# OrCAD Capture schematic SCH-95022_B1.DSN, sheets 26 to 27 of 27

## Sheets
26 Page24 IO-EXP/PCIE SDIO MUX: size A2
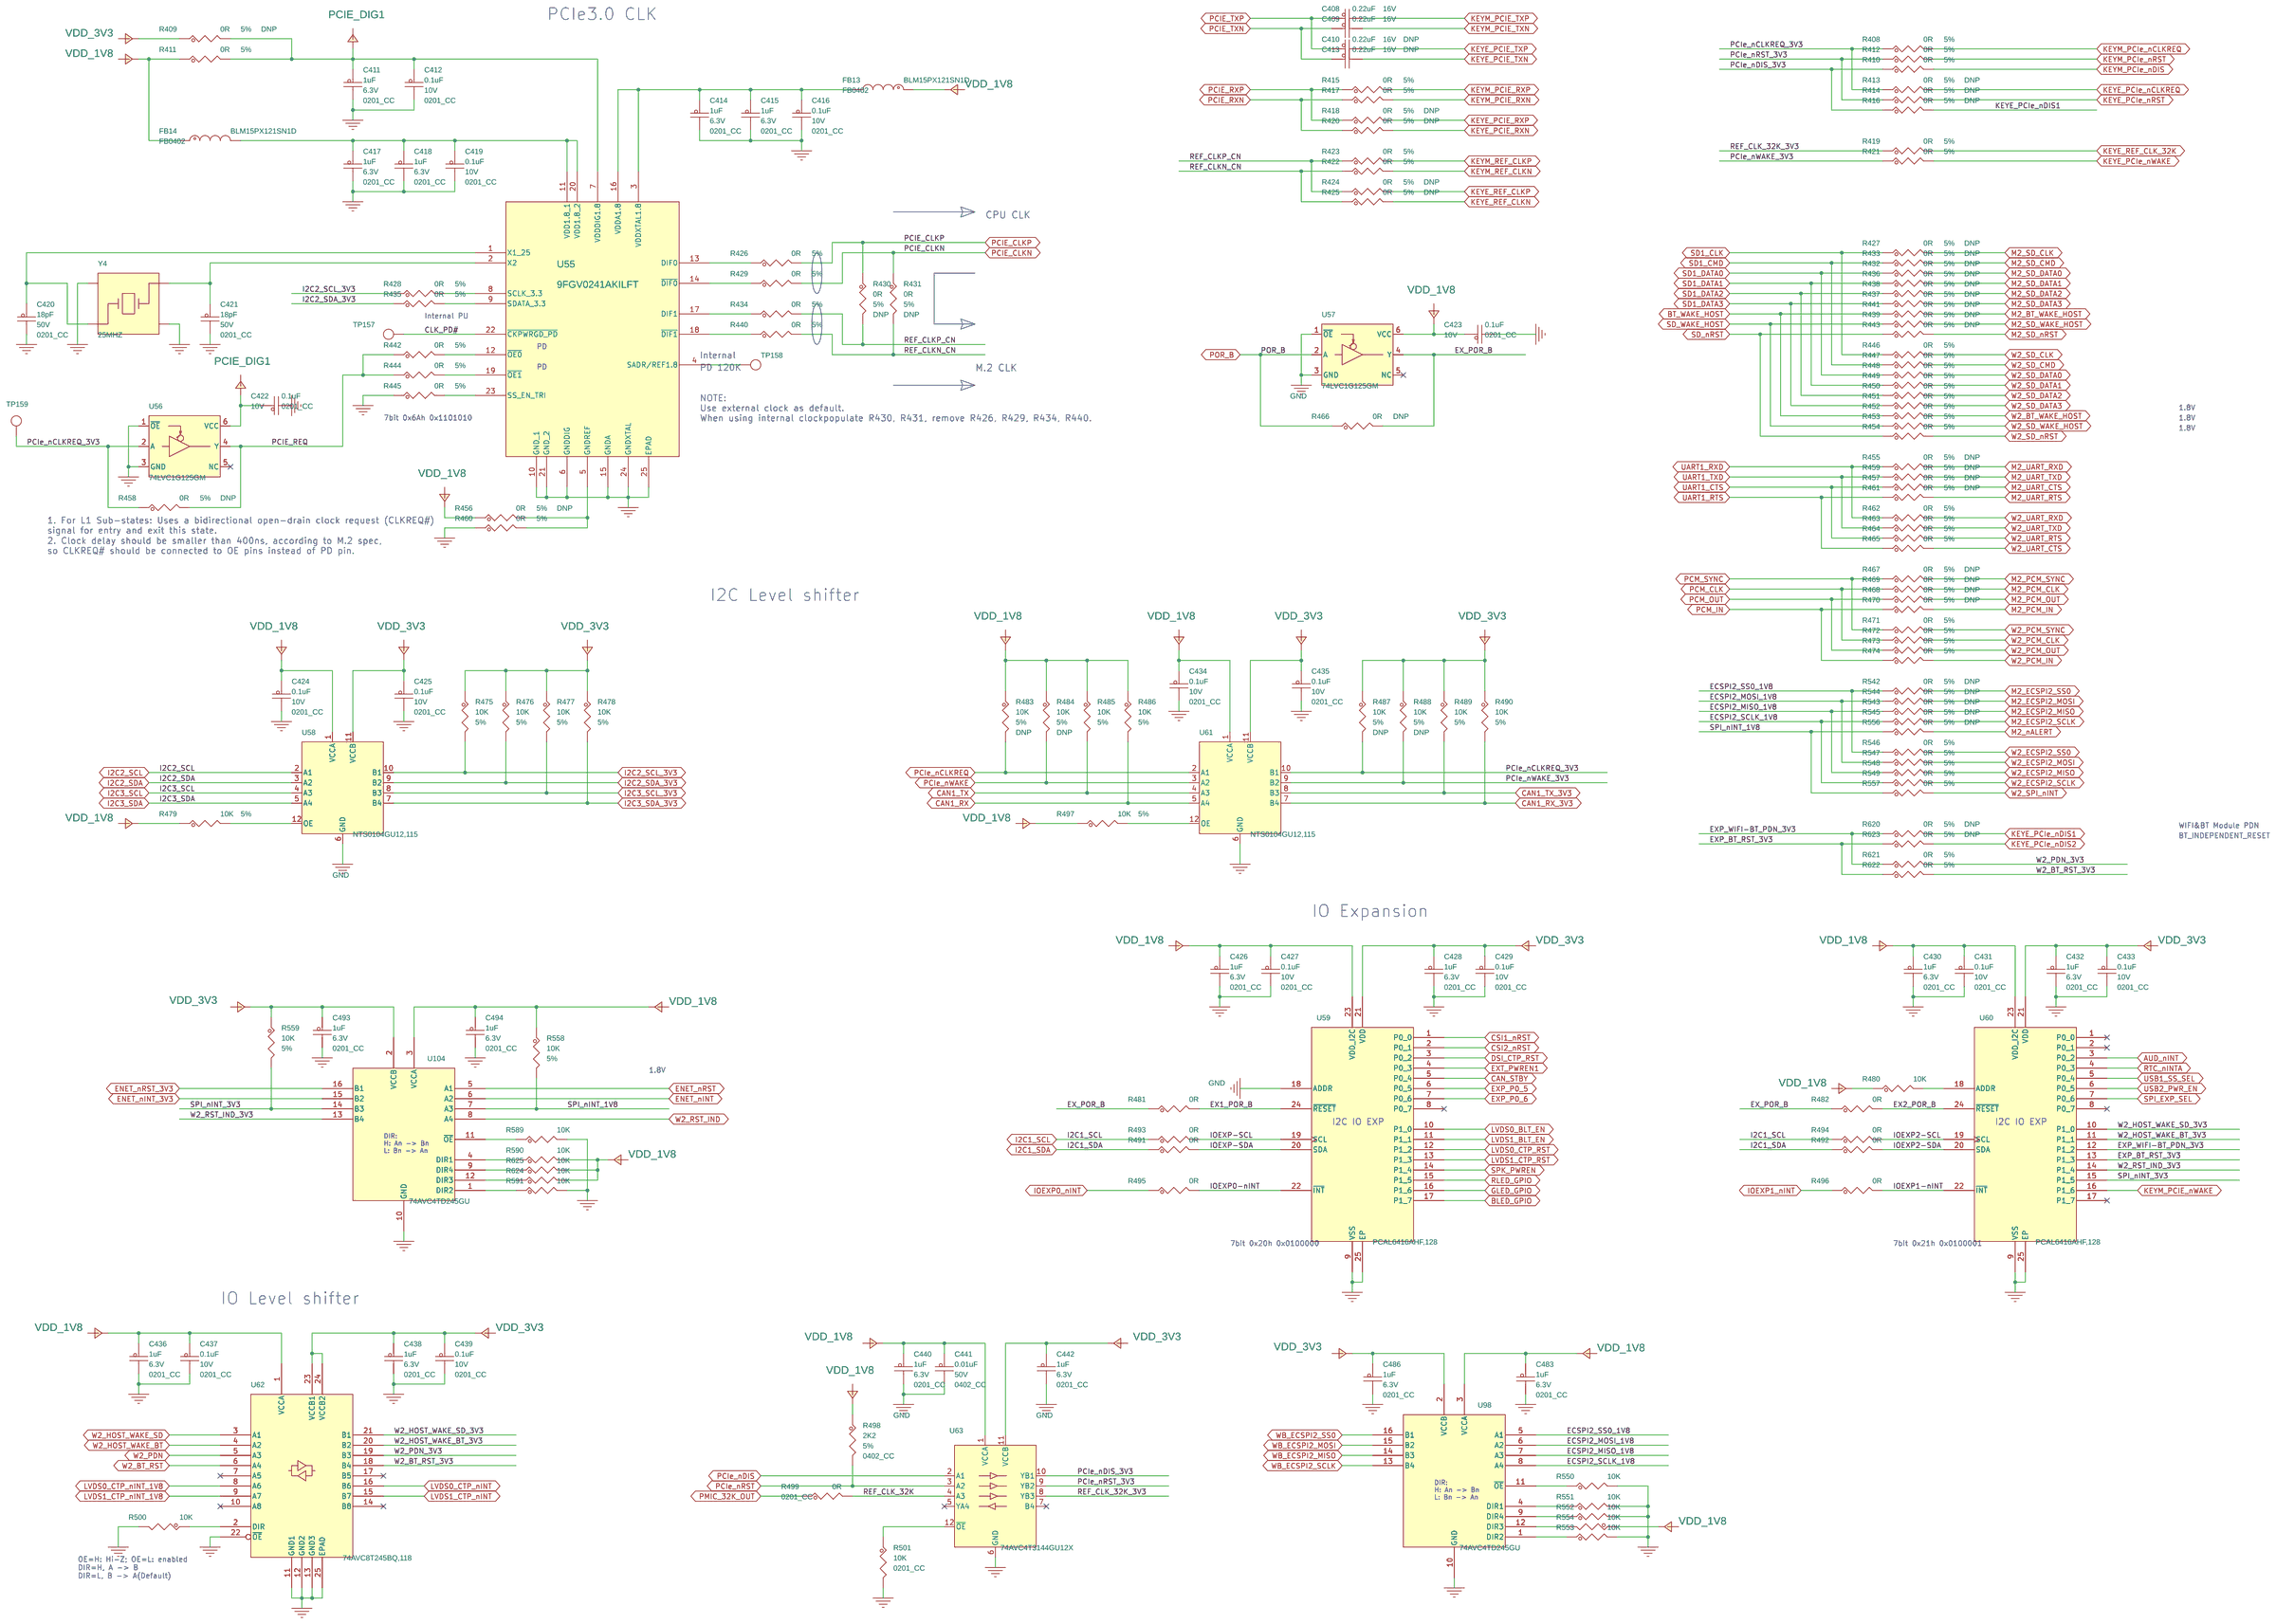
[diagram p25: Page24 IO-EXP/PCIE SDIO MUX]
27 Page21 MicroSD/EXP/BUTTON/LED: size C
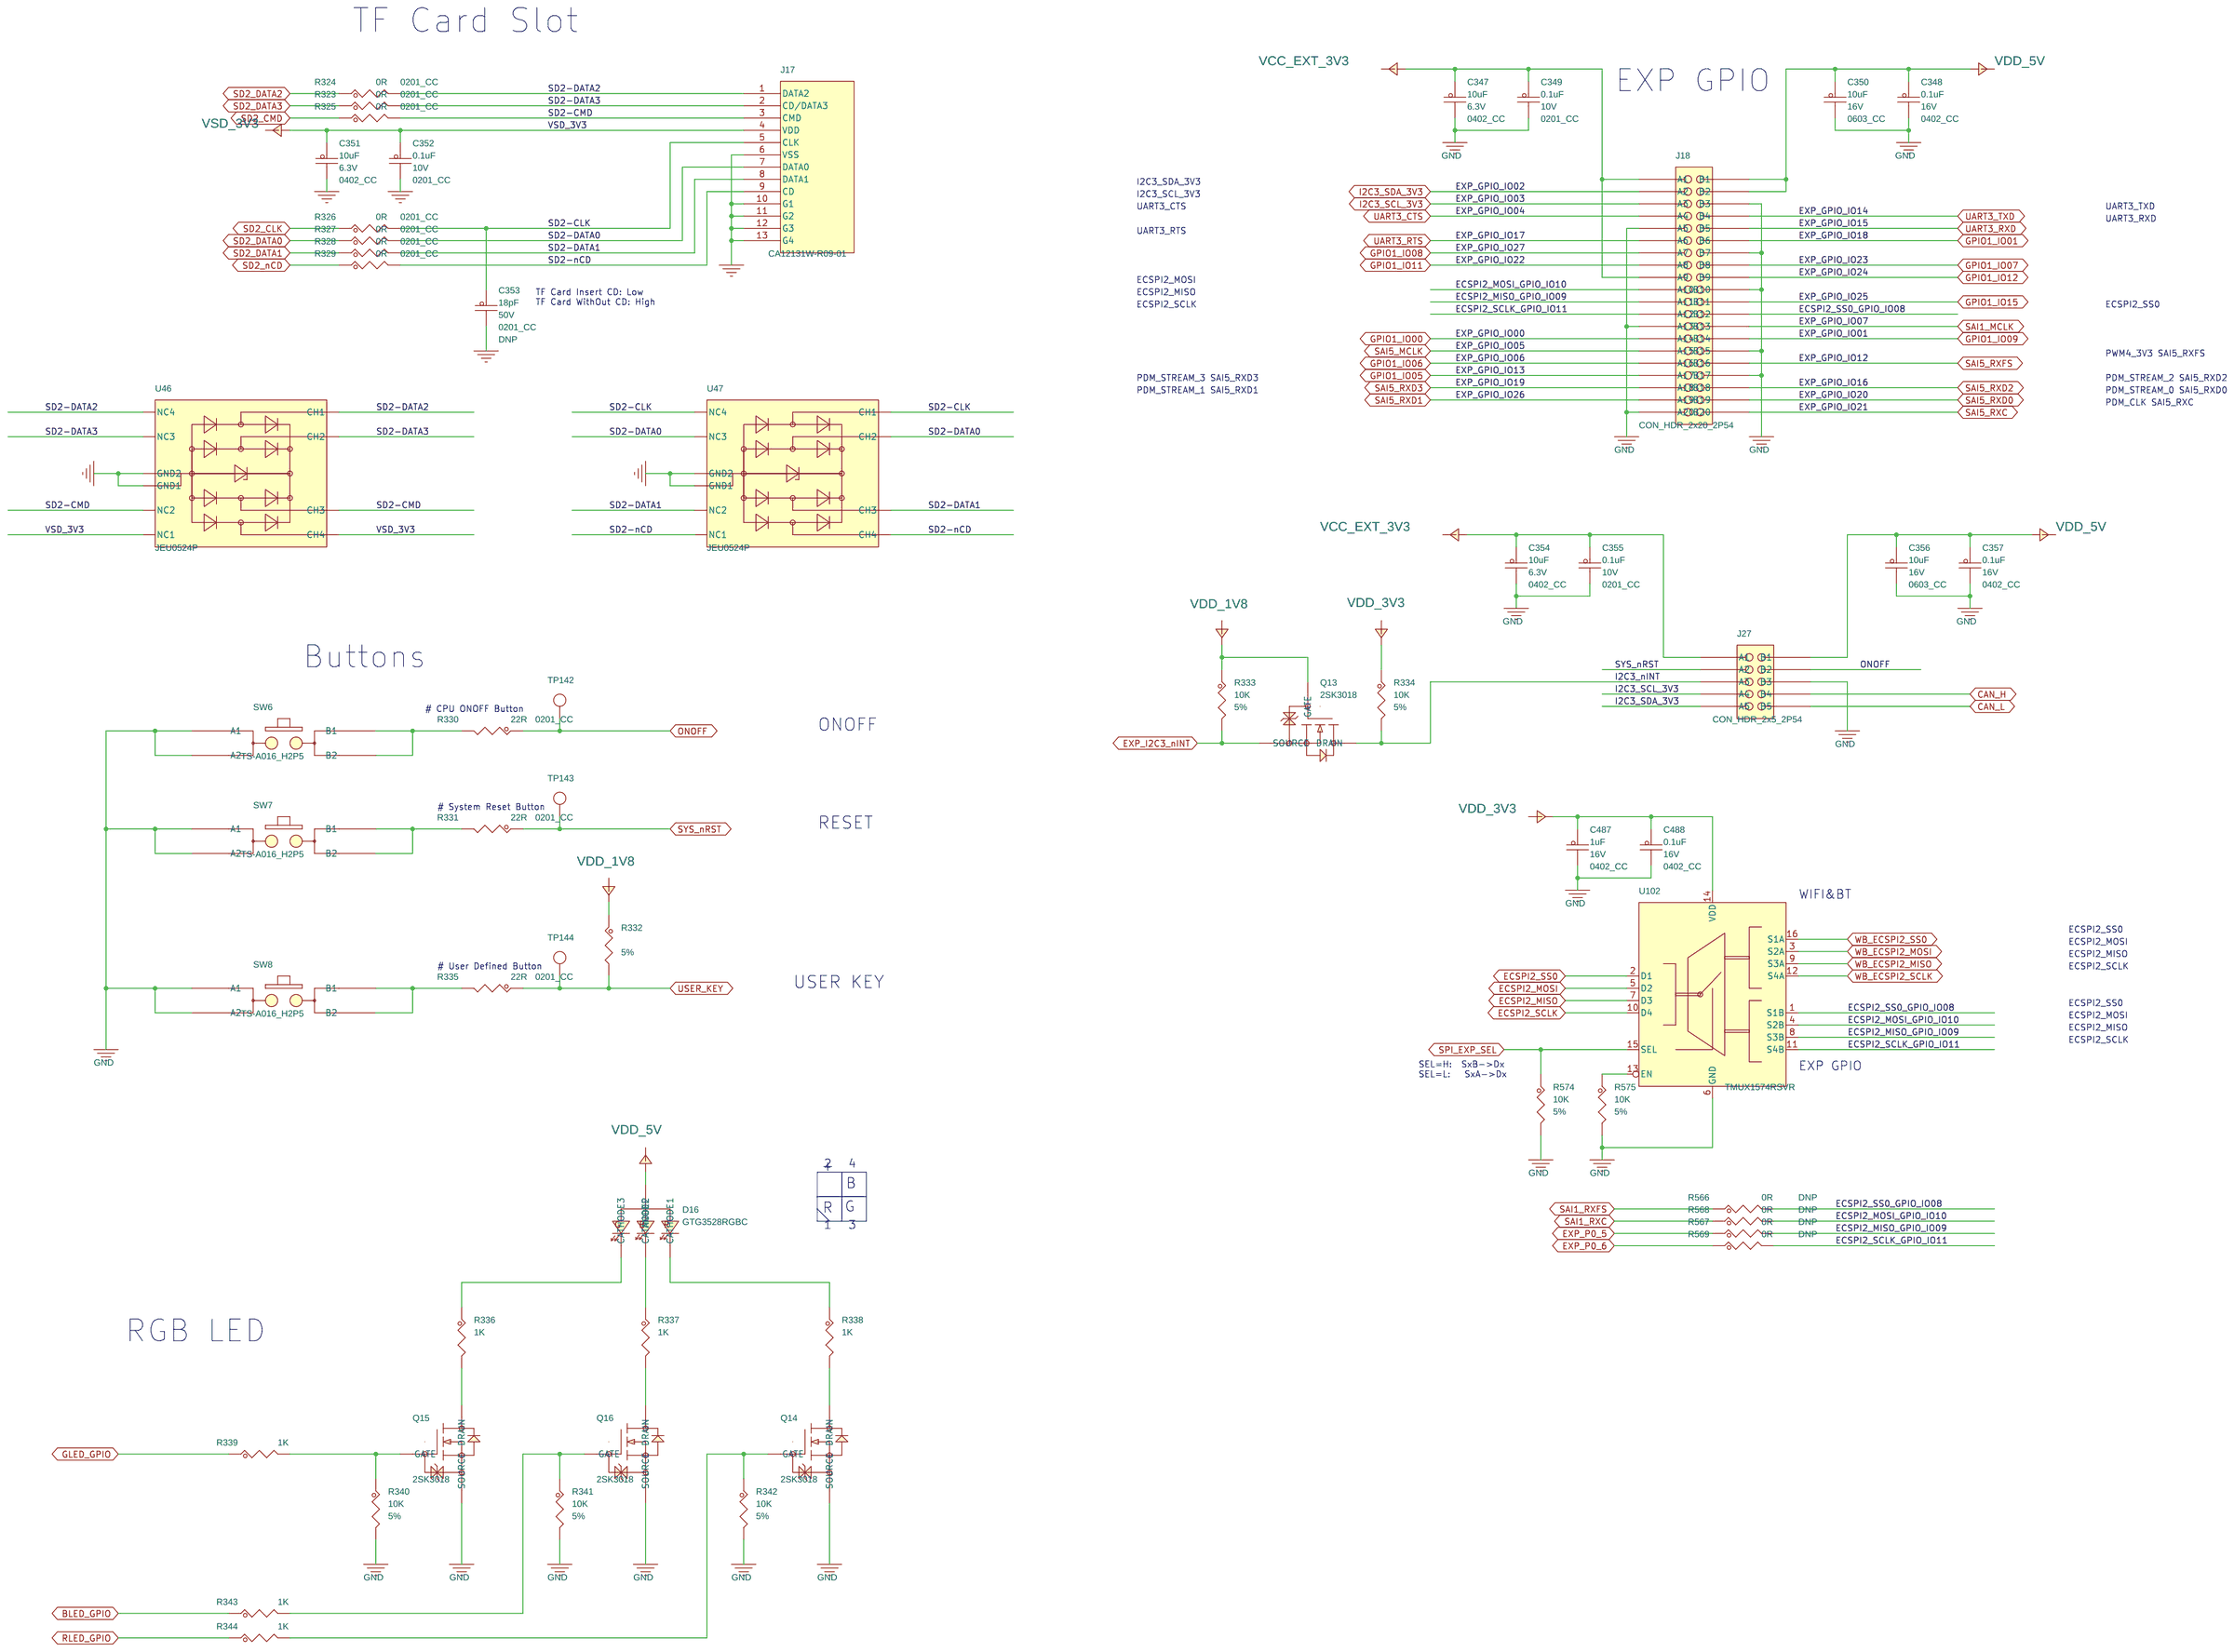
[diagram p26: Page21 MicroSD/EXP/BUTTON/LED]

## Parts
sheet Page21 MicroSD/EXP/BUTTON/LED
C347  10uF  [0402_CC]
C348  0.1uF  [0402_CC]
C349  0.1uF  [0201_CC]
C350  10uF  [0603_CC]
C351  10uF  [0402_CC]
C352  0.1uF  [0201_CC]
C353  18pF  [0201_CC]
C354  10uF  [0402_CC]
C355  0.1uF  [0201_CC]
C356  10uF  [0603_CC]
C357  0.1uF  [0402_CC]
C487  1uF  [0402_CC]
C488  0.1uF  [0402_CC]
D16  GTG3528RGBC  [led4_3p4x3_sm]
J17  CA12131W-R09-01  [MICROSD_14R75x14R50x2R00]
J18  CON_HDR_2x20_2P54  [DIP_HDR2x20_2P54]
J27  CON_HDR_2x5_2P54  [CON_2P54_2x5]
Q13  2SK3018  [SOT_323]
Q14  2SK3018  [SOT_323]
Q15  2SK3018  [SOT_323]
Q16  2SK3018  [SOT_323]
R323  0R  [0201_CC]
R324  0R  [0201_CC]
R325  0R  [0201_CC]
R326  0R  [0201_CC]
R327  0R  [0201_CC]
R328  0R  [0201_CC]
R329  0R  [0201_CC]
R330  22R  [0201_CC]
R331  22R  [0201_CC]
R332  100K  [0402_CC]
R333  10K  [0402_CC]
R334  10K  [0402_CC]
R335  22R  [0201_CC]
R336  1K  [0402_CC]
R337  1K  [0402_CC]
R338  1K  [0402_CC]
R339  1K  [0402_CC]
R340  10K  [0402_CC]
R341  10K  [0402_CC]
R342  10K  [0402_CC]
R343  1K  [0402_CC]
R344  1K  [0402_CC]
R566  0R  [0402_CC]
R567  0R  [0402_CC]
R568  0R  [0402_CC]
R569  0R  [0402_CC]
R574  10K  [0402_CC]
R575  10K  [0402_CC]
SW6  TS-A016_H2P5  [KEY_SMT_4R20x3R25x3R50]
SW7  TS-A016_H2P5  [KEY_SMT_4R20x3R25x3R50]
SW8  TS-A016_H2P5  [KEY_SMT_4R20x3R25x3R50]
TP142  TPAD_020  [tpad_020]
TP143  TPAD_020  [tpad_020]
TP144  TPAD_020  [tpad_020]
U46  JEU0524P  [SLP2510P8-10]
U47  JEU0524P  [SLP2510P8-10]
U102  TMUX1574RSVR  [pqfn16_0p4_2p65x1p85]
sheet Page24 IO-EXP/PCIE SDIO MUX
C408  0.22uF  [0402_CC]
C409  0.22uF  [0402_CC]
C410  0.22uF  [0402_CC]
C411  1uF  [0201_CC]
C412  0.1uF  [0201_CC]
C413  0.22uF  [0402_CC]
C414  1uF  [0201_CC]
C415  1uF  [0201_CC]
C416  0.1uF  [0201_CC]
C417  1uF  [0201_CC]
C418  1uF  [0201_CC]
C419  0.1uF  [0201_CC]
C420  18pF  [0201_CC]
C421  18pF  [0201_CC]
C422  0.1uF  [0201_CC]
C423  0.1uF  [0201_CC]
C424  0.1uF  [0201_CC]
C425  0.1uF  [0201_CC]
C426  1uF  [0201_CC]
C427  0.1uF  [0201_CC]
C428  1uF  [0201_CC]
C429  0.1uF  [0201_CC]
C430  1uF  [0201_CC]
C431  0.1uF  [0201_CC]
C432  1uF  [0201_CC]
C433  0.1uF  [0201_CC]
C434  0.1uF  [0201_CC]
C435  0.1uF  [0201_CC]
C436  1uF  [0201_CC]
C437  0.1uF  [0201_CC]
C438  1uF  [0201_CC]
C439  0.1uF  [0201_CC]
C440  1uF  [0201_CC]
C441  0.01uF  [0402_CC]
C442  1uF  [0201_CC]
C483  1uF  [0201_CC]
C486  1uF  [0201_CC]
C493  1uF  [0201_CC]
C494  1uF  [0201_CC]
FB13  BLM15PX121SN1D  [FB0402]
FB14  BLM15PX121SN1D  [FB0402]
R408  0R  [0402_CC]
R409  0R  [0402_CC]
R410  0R  [0402_CC]
R411  0R  [0402_CC]
R412  0R  [0402_CC]
R413  0R  [0402_CC]
R414  0R  [0402_CC]
R415  0R  [0402_CC]
R416  0R  [0402_CC]
R417  0R  [0402_CC]
R418  0R  [0402_CC]
R419  0R  [0402_CC]
R420  0R  [0402_CC]
R421  0R  [0402_CC]
R422  0R  [0402_CC]
R423  0R  [0402_CC]
R424  0R  [0402_CC]
R425  0R  [0402_CC]
R426  0R  [0402_CC]
R427  0R  [0402_CC]
R428  0R  [0402_CC]
R429  0R  [0402_CC]
R430  0R  [0402_CC]
R431  0R  [0402_CC]
R432  0R  [0402_CC]
R433  0R  [0402_CC]
R434  0R  [0402_CC]
R435  0R  [0402_CC]
R436  0R  [0402_CC]
R437  0R  [0402_CC]
R438  0R  [0402_CC]
R439  0R  [0402_CC]
R440  0R  [0402_CC]
R441  0R  [0402_CC]
R442  0R  [0402_CC]
R443  0R  [0402_CC]
R444  0R  [0402_CC]
R445  0R  [0402_CC]
R446  0R  [0402_CC]
R447  0R  [0402_CC]
R448  0R  [0402_CC]
R449  0R  [0402_CC]
R450  0R  [0402_CC]
R451  0R  [0402_CC]
R452  0R  [0402_CC]
R453  0R  [0402_CC]
R454  0R  [0402_CC]
R455  0R  [0402_CC]
R456  0R  [0402_CC]
R457  0R  [0402_CC]
R458  0R  [0402_CC]
R459  0R  [0402_CC]
R460  0R  [0402_CC]
R461  0R  [0402_CC]
R462  0R  [0402_CC]
R463  0R  [0402_CC]
R464  0R  [0402_CC]
R465  0R  [0402_CC]
R466  0R  [0402_CC]
R467  0R  [0402_CC]
R468  0R  [0402_CC]
R469  0R  [0402_CC]
R470  0R  [0402_CC]
R471  0R  [0402_CC]
R472  0R  [0402_CC]
R473  0R  [0402_CC]
R474  0R  [0402_CC]
R475  10K  [0402_CC]
R476  10K  [0402_CC]
R477  10K  [0402_CC]
R478  10K  [0402_CC]
R479  10K  [0402_CC]
R480  10K  [0402_CC]
R481  0R  [0402_CC]
R482  0R  [0402_CC]
R483  10K  [0402_CC]
R484  10K  [0402_CC]
R485  10K  [0402_CC]
R486  10K  [0402_CC]
R487  10K  [0402_CC]
R488  10K  [0402_CC]
R489  10K  [0402_CC]
R490  10K  [0402_CC]
R491  0R  [0402_CC]
R492  0R  [0402_CC]
R493  0R  [0402_CC]
R494  0R  [0402_CC]
R495  0R  [0402_CC]
R496  0R  [0402_CC]
R497  10K  [0402_CC]
R498  2K2  [0402_CC]
R499  0R  [0201_CC]
R500  10K  [0402_CC]
R501  10K  [0201_CC]
R542  0R  [0402_CC]
R543  0R  [0402_CC]
R544  0R  [0402_CC]
R545  0R  [0402_CC]
R546  0R  [0402_CC]
R547  0R  [0402_CC]
R548  0R  [0402_CC]
R549  0R  [0402_CC]
R550  10K  [0402_CC]
R551  10K  [0402_CC]
R552  10K  [0402_CC]
R553  10K  [0402_CC]
R554  10K  [0402_CC]
R556  0R  [0402_CC]
R557  0R  [0402_CC]
R558  10K  [0402_CC]
R559  10K  [0402_CC]
R589  10K  [0402_CC]
R590  10K  [0402_CC]
R591  10K  [0402_CC]
R620  0R  [0402_CC]
R621  0R  [0402_CC]
R622  0R  [0402_CC]
R623  0R  [0402_CC]
R624  10K  [0402_CC]
R625  10K  [0402_CC]
TP157  TPAD_020  [tpad_020]
TP158  TPAD_020  [tpad_020]
TP159  TPAD_050  [TPAD_050]
U55  9FGV0241AKILFT  [qfn24_0p5_4x4_ep2p2]
U56  74LVC1G125GM  [udfn6_1x1p5mm]
U57  74LVC1G125GM  [udfn6_1x1p5mm]
U58  NTS0104GU12,115  [xqfn12_0p4_1p8x2p1]
U59  PCAL6416AHF,128  [qfn24_4X4_ep2p25mm]
U60  PCAL6416AHF,128  [qfn24_4X4_ep2p25mm]
U61  NTS0104GU12,115  [xqfn12_0p4_1p8x2p1]
U62  74AVC8T245BQ,118  [QFN24_0P5_5P6X3P6_EP]
U63  74AVC4T3144GU12X  [uqfn12_1p7x2mm]
U98  74AVC4TD245GU  [pqfn16_0p4_2p65x1p85]
U104  74AVC4TD245GU  [pqfn16_0p4_2p65x1p85]
Y4  25MHZ  [xtlosc4_3p2x2p5mm_sm]

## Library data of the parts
C347 C351 C354 = CAP_NP: CAP CER 10UF 6.3V 20% X5R 0402; AGILE_PN: 150-79163; CAD_APPROVED: Yes; FPLIST: CC0402_25,CC0402_HD,0402_CC; HEIGHT: 0.65 MM; MFG_NAME01: SAMSUNG; MFG_PN01: CL05A106MQ5NUNC; Polyhex_Number: PD.005.0031; ROHS: Yes; Tolerance: 20%; VOLTAGE: 6.3V
C348 C357 C488 = CAP_NP: CAP CER 0.1UF 16V 10% X5R 0402; CAD_APPROVED: Yes; FPLIST: CC0402_25,CC0402_HD,0402_CC,capc0402_l; HEIGHT: 0.55MM; MFG_NAME01: SAMSUNG; MFG_PN01: CL05B104K05NNNC; Polyhex_Number: PD.005.0036; ROHS: Yes; Tolerance: 10%; VOLTAGE: 16V
C349 C352 C355 C412 C416 C419 C422-C425 C427 C429 C431 C433-C435 C437 C439 = CAP_NP: CAP CER 0.1uF 10V 20% X5R 0201; CAD_APPROVED: Yes; HEIGHT: 0.35MM; MFG_NAME01: SAMSUNG; MFG_PN01: CL03A104KP3NNNC; Package Size: 0201; Package Type: 7” reel; Polyhex_Number: PD.005.0054; ROHS: Yes; Tolerance: 20%; VOLTAGE: 10V
C350 C356 = CAP_NP: CAP CER 10uF 16V 10% X5R 0603; CAD_APPROVED: Yes; HEIGHT: 0.55 MM; MFG_NAME01: SAMSUNG; MFG_PN01: CL10A106MO8NQN; Package Size: 0603; Polyhex_Number: PD.005.0001; ROHS: Yes; Tolerance: 10%; VOLTAGE: 16V
C353 = CAP_NP: CAP CER 18pF 50V 5% C0G 0201; ASSY_OPT: DNP; CAD_APPROVED: Yes; HEIGHT: 0.35MM; MFG_NAME01: SAMSUNG; MFG_PN01: CL03C180JB3NNNH; Package Size: 0201; Package Type: 7” reel; Polyhex_Number: PD.005.0033; ROHS: Yes; Tolerance: 5%; VOLTAGE: 50V
C487 = CAP_NP: CAP CER 1UF 16V 10% X5R 0402; CAD_APPROVED: Yes; FPLIST: CC0402_25,CC0402_HD,0402_CC,capc0402_l; HEIGHT: 0.55MM; MFG_NAME01: SAMSUNG; MFG_PN01: CL05A105KO5NNNC; Polyhex_Number: PD.005.0099; ROHS: Yes; Tolerance: 10%; VOLTAGE: 16V
D16 = LED_GPLY6900: LED RGB MULTI 20MA SMT; AGILE_PN: 370-76731; CAD_APPROVED: Yes; HEIGHT: 2.04 MM; MFG_NAME01: HYXNDQ; Polyhex_Number: PD.020.0076; VOLTAGE: 1.7-3.7V
J17 = TFCARD_SOCKET: CON 9 MICRO SD CARD PUSH SMT 1.9MM; Created by: JJJ; HEIGHT: 1.9mm; MFG_NAME01: JINRUN; Polyhex_Number: PD.010.0025; Priority: A
J18 = CON_HDR_2x20_2P54: CON HEADER PH2.54x2.5 2x20P PA6.0 PC3.0 180 YELLOW; MFG_NAME01: XINGUANHUIELECTRONICS; MFG_PN01: PH1-H220-S9Y-G0; Polyhex_Number: PD.011.0171
J27 = CON_HDR_2X5_2P54: CON HEADER 2X5PIN 2.54MM DIP; MFG_NAME01: WENZHANGJIMEI; MFG_PN01: PH2.54X2.5_2X5P_DIP; Polyhex_Number: PD.011.0173
Q13-Q16 = 2SK3018_SOT323: NMOS SW 30V 100mA SOT-323; MFG_NAME01: CHANGJING ELECTRONICS; Polyhex_Number: PD.014.0008
R323-R329 R499 = RES: RES MF ZERO OHM 1/20W 5% 0201; AGILE_PN: 470-82323; CAD_APPROVED: Yes; FPLIST: RC0201,0201_CC; HEIGHT: 0.26MM; MFG_NAME01: YAGEO; MFG_PN01: RC0201JR-070RL; Polyhex_Number: PD.004.0171; ROHS: Yes; Temp Range: -55°C ~ 125°C; Temp_Range: -55°C ~ 125°C; Tolerance: 5%; VOLTAGE: 25V
R330 R331 R335 = RES: RES MF 22 OHM 1/20W 5% 0201; AGILE_PN: 470-82323; CAD_APPROVED: Yes; FPLIST: RC0201,0201_CC; HEIGHT: 0.26MM; MFG_NAME01: YAGEO; MFG_PN01: RC0201JR-0722RL; Polyhex_Number: PD.004.0173; ROHS: Yes; Temp Range: -55°C ~ 125°C; Temp_Range: -55°C ~ 125°C; Tolerance: 5%; VOLTAGE: 25V
R332 = RES: RES MF 100K 1/16W 5% 0402; AGILE_PN: 470-75597; CAD_APPROVED: Yes; FPLIST: RC0402_25,RC0402_HD,0402_CC; HEIGHT: 0.40 MM; MFG_NAME01: YAGEO; MFG_PN01: RC0402JR-07100KL; Polyhex_Number: PD.004.0004; ROHS: Yes; Temp Range: -55C to +155C; Temp_Range: -55C to +155C; Tolerance: 5%; VOLTAGE: 50V
R333 R334 R340-R342 R475-R480 R485 R486 R489 R490 R497 R500 R550-R554 R558 R559 R574 R575 R589-R591 R624 R625 = RES: RES MF 10K 1/16W 5% 0402; AGILE_PN: 470-75557; CAD_APPROVED: Yes; FPLIST: RC0402_25,RC0402_HD,0402_CC; HEIGHT: 0.4 MM; MFG_NAME01: YAGEO; MFG_PN01: RC0402JR-0710KL; Polyhex_Number: PD.004.0010; ROHS: Yes; Tolerance: 5%; VOLTAGE: 50V
R336-R339 R343 R344 = RES: RES MF 1K 1/16W 5% 0402; CAD_APPROVED: Yes; HEIGHT: 0.4 MM; MFG_NAME01: YAGEO; MFG_PN01: RC0402JR-071KL; Polyhex_Number: PD.004.0007; ROHS: Yes; Tolerance: 5%
R409 R413 R414 R416 R418 R420 R424 R425 R427 R430-R433 R436-R439 R441 R443 R455-R459 R461 R466-R470 R542-R545 R556 R566-R569 R620 R623 = RES: RES MF ZERO OHM 1/16W 5% 0402; AGILE_PN: 470-75394; ASSY_OPT: DNP; CAD_APPROVED: Yes; FPLIST: RC0402_25,RC0402_HD,RC0402_X2,0402_CC; HEIGHT: 0.45 MM; MFG_NAME01: YAGEO; MFG_PN01: RC0402JR-070RL; Polyhex_Number: PD.004.0009; ROHS: Yes; Tolerance: 5%; VOLTAGE: 50V
SW6-SW8 = SW_PB_ESW: SW SPST MOM NO PB TACT 50mA 12V SMT; AGILE_PN: 510-77562; CAD_APPROVED: Yes; HEIGHT: 5MM; MFG_NAME01: HUAXINR; Polyhex_Number: PD.015.0009; ROHS: Yes
TP142-TP144 TP157 TP158 = TESTLOOP: TEST POINT PAD 0.5MM DIA SMT, NO PART TO ORDER; AGILE_PN: 211-77484; ASSY_OPT: DNP; CAD_APPROVED: Yes; HEIGHT: 0.1MM; MFG_NAME01: NOT A COMPONENT; MFG_PN01: NOT A COMPONENT; Polyhex_Number: TEST POINT; ROHS: Yes
U46 U47 = TVS_ARRAY: TVS Diode array for ESD Protection 0.65pF; AGILE_PN: 480-79837; CAD_APPROVED: Yes; EN: 301-0-01726; HEIGHT: 0.5MM; MFG_NAME01: Jiejie Microelectronics; Polyhex_Number: PD.020.0022; ROHS: Yes; Temp Range: -55C to +125C; Temp_Range: -55C to +125C
U102 = TMUX1574RSVR_A: IC MUX SW SPDT 1.8V UQFN16; AGILE_PN: 312-82341; MFG_NAME01: TEXAS INSTRUMENTS; Polyhex_Number: PD.008.0333
C408 C409 = CAP_NP: CAP CER 0.22uF 16V 10% X5R 0402; AGILE_PN: 150-79999; CAD_APPROVED: Yes; FPLIST: CC0402_25,CC0402_HD,0402_CC; HEIGHT: 0.55MM; MFG_NAME01: SAMSUNG; MFG_PN01: CL05B224KO5NNNC; Package Size: 0402; Polyhex_Number: PD.005.0050; ROHS: Yes; Temp Range: -55°C to +85°C; Temp_Range: -55°C to +85°C; Tolerance: 10%; VOLTAGE: 16V
C410 C413 = CAP_NP: CAP CER 0.22uF 16V 10% X5R 0402; AGILE_PN: 150-79999; ASSY_OPT: DNP; CAD_APPROVED: Yes; FPLIST: CC0402_25,CC0402_HD,0402_CC; HEIGHT: 0.55MM; MFG_NAME01: SAMSUNG; MFG_PN01: CL05B224KO5NNNC; Package Size: 0402; Polyhex_Number: PD.005.0050; ROHS: Yes; Temp Range: -55°C to +85°C; Temp_Range: -55°C to +85°C; Tolerance: 10%; VOLTAGE: 16V
C411 C414 C415 C417 C418 C426 C428 C430 C432 C436 C438 C440 C442 C483 C486 C493 C494 = CAP_NP: CAP CER 1uF 6.3V 10% X5R 0201; AGILE_PN: 150-79407; CAD_APPROVED: Yes; FPLIST: CC0201,CC0201_HD,0201_CC,0201_CC_012SM_NSP; HEIGHT: 0.35MM; MFG_NAME01: SAMSUNG; MFG_PN01: CL03A105KQ3CSNH; Package Size: 0201; Package Type: 7” reel; Polyhex_Number: PD.005.0030; ROHS: Yes; Tolerance: 10%; VOLTAGE: 6.3V
C420 C421 = CAP_NP: CAP CER 18pF 50V 5% C0G 0201; CAD_APPROVED: Yes; HEIGHT: 0.35MM; MFG_NAME01: SAMSUNG; MFG_PN01: CL03C180JB3NNNH; Package Size: 0201; Package Type: 7” reel; Polyhex_Number: PD.005.0033; ROHS: Yes; Tolerance: 5%; VOLTAGE: 50V
C441 = CAP_NP: CAP CER 0.01uF 50V 10% X7R 0402; CAD_APPROVED: Yes; FPLIST: CC0402_25,CC0402_HD,0402_CC,capc0402_l; HEIGHT: 0.55 MM; MFG_NAME01: SAMSUNG; MFG_PN01: CL05B103KB5NNNC; Package Size: 0402; Polyhex_Number: PD.005.0006; ROHS: Yes; Tolerance: 10%; VOLTAGE: 50V
FB13 FB14 = Ferrite_Bead: FERRITE 0402 120Ohm@100MHz 2A; HEIGHT: 0.5mm; Irms: <Irms>; MFG_NAME01: Murata; Polyhex_Number: PD.009.0006; Temp Range: -55C to +125C; Temp_Range: -55C to +125C
R408 R410-R412 R415 R417 R419 R421-R423 R426 R428 R429 R434 R435 R440 R442 R444-R454 R460 R462-R465 R471-R474 R481 R482 R491-R496 R546-R549 R557 R621 R622 = RES: RES MF ZERO OHM 1/16W 5% 0402; AGILE_PN: 470-75394; CAD_APPROVED: Yes; FPLIST: RC0402_25,RC0402_HD,RC0402_X2,0402_CC; HEIGHT: 0.45 MM; MFG_NAME01: YAGEO; MFG_PN01: RC0402JR-070RL; Polyhex_Number: PD.004.0009; ROHS: Yes; Tolerance: 5%; VOLTAGE: 50V
R483 R484 R487 R488 = RES: RES MF 10K 1/16W 5% 0402; AGILE_PN: 470-75557; ASSY_OPT: DNP; CAD_APPROVED: Yes; FPLIST: RC0402_25,RC0402_HD,0402_CC; HEIGHT: 0.4 MM; MFG_NAME01: YAGEO; MFG_PN01: RC0402JR-0710KL; Polyhex_Number: PD.004.0010; ROHS: Yes; Tolerance: 5%; VOLTAGE: 50V
R498 = RES: RES MF 2K2 1/16W 5% 0402; CAD_APPROVED: Yes; HEIGHT: 0.23mm; MFG_NAME01: YAGEO; MFG_PN01: RC0402JR-072K2L; Polyhex_Number: PD.004.0098; ROHS: Yes; Tolerance: 5%; VOLTAGE: 50V
R501 = RES: RES MF 10K 1/20W 5% 0201; CAD_APPROVED: Yes; HEIGHT: 0.23mm; MFG_NAME01: YAGEO; MFG_PN01: RC0201JR-0710KL; Polyhex_Number: PD.004.0069; ROHS: Yes; Tolerance: 5%; VOLTAGE: 25V
TP159 = TESTLOOP: TEST POINT PAD 50MIL DIA SMT, NO PART TO ORDER; AGILE_PN: 211-76644; ASSY_OPT: DNP; CAD_APPROVED: Yes; HEIGHT: 0.1MM; MFG_NAME01: NOTACOMPONENT; MFG_PN01: NOTACOMPONENT; Polyhex_Number: TEST POINT; ROHS: Yes
U55 = 9FGV0241AKLF_24P: IC CLK GEN 2-OUTPUT VERY LOW POWER PCIE 1.7-1.9V VFQFPN24; AGILE_PN: 312-81024; CAD_APPROVED: Yes; HEIGHT: 1 MM; MFG_NAME01: RENESAS IDT; Polyhex_Number: PD.008.0299; ROHS: Yes; VOLTAGE: 1.7-1.9V
U56 U57 = 74AUP1G125GN_6P: IC BUF DRV 3STATE 1.65V-5.5V XSON6; AGILE_PN: 315-82475; CAD_APPROVED: yes; HEIGHT: 0.5mm; MFG_NAME01: NEXPERIA; Package Size: 1.5x1.05x0.5mm; Polyhex_Number: PD.008.0323; ROHS: YES
U58 U61 = NTS0104GU12_12P: IC DUAL VXLTR XCVR 4BIT 1.65-3.6/2.3-5.5V XQFN12; AGILE_PN: 312-82046; CAD_APPROVED: Yes; HEIGHT: 0.5MM; MFG_NAME01: NXP SEMICONDUCTORS; Polyhex_Number: PD.008.0328; ROHS: Yes; Temp Range: -40 to +125C; VOLTAGE: 1.65-3.6/2.3-5.5V
U59 U60 = PCAL6416AHF_QFN24: IC 16-BIT I2C-BUS I/O EXPANDER 1.65V-5.5V HWQFN24; AGILE_PN: 312-82343; CAD_APPROVED: Yes; HEIGHT: 0.8 MM; MFG_NAME01: NXP SEMICONDUCTORS; Polyhex_Number: PD.008.0329; ROHS: Yes; VOLTAGE: 1.65-5.5V
U62 = SN74AVC8T245: IC VXLTR 8BIT TS 0.8-3.6V DHVQFN24; AGILE_PN: 312-82315; CAD_APPROVED: Yes; HEIGHT: 1MM; MFG_NAME01: NEXPERIA; Polyhex_Number: PD.008.0330; ROHS: Yes; Temp Range: -40 to  +125; VOLTAGE: 0.8-3.6
U63 = 74AVC4T3144GU12: 74AVC4T3144GU12,XQFN12,1.70*2.0,4-bit dual-supply buffer/level translator;3-state; 3D_Mechanical_Footprint_File: ftp://fcl.am.freescale.net/ALLEGRO/step/uqfn12_1p7x2mm.STEP; CAD_APPROVED: Yes; HEIGHT: 0.55 MM; MFG_NAME01: NEXPERIA; Polyhex_Number: PD.008.0331; ROHS: Yes; VOLTAGE: 0.9-3.6V
U98 U104 = 74AVC4TD245GU_XQFN16: IC DUAL SUPPLY XCVR VXLTR 4BIT 0.8-3.6V XQFN16; 3D_Mechanical_Footprint_File: http://fcl.am.freescale.net/ALLEGRO/step/pqfn16_0p4_2p65x1p85.STEP; AGILE_PN: 312-83790; CAD_APPROVED: Yes; HEIGHT: 0.5 MM; MFG_NAME01: NEXPERIA; Polyhex_Number: PD.008.0332; ROHS: Yes; Temp Range: -40  °C - +125 °C
Y4 = XTAL_13Y: XTAL 25MHZ 12pF 10PPM SMT 3.2X2.5MM; AGILE_PN: 230-77392; CAD_APPROVED: Yes; HEIGHT: 0.60MM; MFG_NAME01: HOSONIC; MFG_PN01: E3SB25E00000VE; Polyhex_Number: PD.018.0004; ROHS: Yes

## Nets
GND: C347.2 C348.2 C349.2 C350.2 C351.2 C352.2 C353.2 C354.2 C355.2 C356.2 C357.2 C411.2 C412.2 C414.2 C415.2 C416.2 C417.2 C418.2 C419.2 C420.2 C421.2 C422.2 C423.2 C424.2 C425.2 C426.2 C427.2 C428.2 C429.2 C430.2 C431.2 C432.2 C433.2 C434.2 C435.2 C436.2 C437.2 C438.2 C439.2 C440.2 C441.2 C442.2 C483.2 C486.2 C487.2 C488.2 C493.2 C494.2 J17.6(VSS) J17.10(G1) J17.11(G2) J17.12(G3) J17.13(G4) J18.6(B3) J18.9(A5) J18.14(B7) J18.20(B10) J18.25(A13) J18.30(B15) J18.34(B17) J18.39(A20) J27.6(B3) Q14.2(SOURCE) Q15.2(SOURCE) Q16.2(SOURCE) R340.2 R341.2 R342.2 R445.1 R460.1 R500.2 R501.2 R550.2 R551.2 R552.2 R553.2 R574.2 R575.2 R589.2 R591.2 SW6.1(A1) SW6.2(A2) SW7.1(A1) SW7.2(A2) SW8.1(A1) SW8.2(A2) U46.3(GND1) U46.8(GND2) U47.3(GND1) U47.8(GND2) U55.6(GNDDIG) U55.10(GND_1) U55.15(GNDA) U55.21(GND_2) U55.24(GNDXTAL) U55.25(EPAD) U56.1(~{OE}) U56.3(GND) U57.1(~{OE}) U57.3(GND) U58.6(GND) U59.9(VSS) U59.18(ADDR) U59.25(EP) U60.9(VSS) U60.25(EP) U61.6(GND) U62.11(GND1) U62.12(GND2) U62.13(GND3) U62.22(~{OE}) U62.25(EPAD) U63.6(GND) U98.10(GND) U102.6(GND) U104.10(GND) Y4.2 Y4.4 ; also on sheet 4 5 7 8 9 10 11 12 13 14 15 16 17 18 19 20 21 22 23 24 25
VCC_EXT_3V3: C347.1 C349.1 C354.1 C355.1 J18.1(A1) J18.17(A9) J27.1(A1) ; also on sheet 11 19 20 21 23 24 25
VDD_1V8: C423.1 C424.1 C426.1 C427.1 C430.1 C431.1 C434.1 C436.1 C437.1 C440.1 C441.1 C483.1 C494.1 FB13.1 FB14.1 Q13.1(GATE) R332.1 R333.1 R411.1 R456.1 R479.1 R480.1 R483.1 R484.1 R485.1 R486.1 R497.1 R498.1 R554.1 R558.1 R590.2 R624.2 R625.2 U57.6(VCC) U58.1(VCCA) U59.23(VDD_I2C) U60.23(VDD_I2C) U61.1(VCCA) U62.1(VCCA) U63.1(VCCA) U98.3(VCCA) U104.3(VCCA) ; also on sheet 4 5 6 9 10 12 16 18 21 22 23 24 25
VDD_3V3: C425.1 C428.1 C429.1 C432.1 C433.1 C435.1 C438.1 C439.1 C442.1 C486.1 C487.1 C488.1 C493.1 R334.1 R409.1 R475.1 R476.1 R477.1 R478.1 R487.1 R488.1 R489.1 R490.1 R559.1 U58.11(VCCB) U59.21(VDD) U60.21(VDD) U61.11(VCCB) U62.23(VCCB1) U62.24(VCCB2) U63.11(VCCB) U98.2(VCCB) U102.14(VDD) U104.2(VCCB) ; also on sheet 4 10 11 12 13 14 15 16 17 18 20 22 24
VDD_5V: C348.1 C350.1 C356.1 C357.1 D16.2(ANODE) J18.2(B1) J18.4(B2) J27.2(B1) ; also on sheet 11 12 13 18 19 20 24
AUD_nINT: U60.3(P0_2) ; also on sheet 18
BLED_GPIO: R343.1 U59.17(P1_7)
BT_WAKE_HOST: R441.1 R452.1 ; also on sheet 6
CAN1_RX: R486.2 U61.5(A4) ; also on sheet 6
CAN1_RX_3V3: R490.2 U61.7(B4) ; also on sheet 24
CAN1_TX: R485.2 U61.4(A3) ; also on sheet 6
CAN1_TX_3V3: R489.2 U61.8(B3) ; also on sheet 24
CAN_H: J27.8(B4) ; also on sheet 24
CAN_L: J27.10(B5) ; also on sheet 24
CAN_STBY: U59.5(P0_4) ; also on sheet 24
CLK_PD#: TP157.1(Pin1) U55.22(~{CKPWRGD_PD})
CSI1_nRST: U59.1(P0_0) ; also on sheet 25
CSI2_nRST: U59.2(P0_1) ; also on sheet 25
DSI_CTP_RST: U59.3(P0_2) ; also on sheet 25
ECSPI2_MISO: U102.7(D3) ; also on sheet 6
ECSPI2_MISO_1V8: R543.1 R548.1 U98.7(A3)
ECSPI2_MISO_GPIO_IO09: J18.21(A11) R567.2 U102.8(S3B)
ECSPI2_MOSI: U102.5(D2) ; also on sheet 6
ECSPI2_MOSI_1V8: R544.1 R547.1 U98.6(A2)
ECSPI2_MOSI_GPIO_IO10: J18.19(A10) R568.2 U102.4(S2B)
ECSPI2_SCLK: U102.10(D4) ; also on sheet 6
ECSPI2_SCLK_1V8: R545.1 R549.1 U98.8(A4)
ECSPI2_SCLK_GPIO_IO11: J18.23(A12) R569.2 U102.11(S4B)
ECSPI2_SS0: U102.2(D1) ; also on sheet 6
ECSPI2_SS0_1V8: R542.1 R546.1 U98.5(A1)
ECSPI2_SS0_GPIO_IO08: J18.24(B12) R566.2 U102.1(S1B)
ENET_nINT: U104.6(A2) ; also on sheet 6
ENET_nINT_3V3: U104.15(B2) ; also on sheet 16
ENET_nRST: U104.5(A1) ; also on sheet 6
ENET_nRST_3V3: U104.16(B1) ; also on sheet 16
EX1_POR_B: R481.2 U59.24(~{RESET})
EX2_POR_B: R482.2 U60.24(~{RESET})
EX_POR_B: R466.2 R481.1 R482.1 U57.4(Y)
EXP_BT_RST_3V3: R622.1 R623.1 U60.13(P1_3)
EXP_I2C3_nINT: Q13.2(SOURCE) R333.2 ; also on sheet 6
EXP_P0_5: R567.1 U59.6(P0_5)
EXP_P0_6: R569.1 U59.7(P0_6)
EXP_WIFI-BT_PDN_3V3: R620.1 R621.1 U60.12(P1_2)
EXT_PWREN1: U59.4(P0_3) ; also on sheet 20
GLED_GPIO: R339.1 U59.16(P1_6)
GPIO1_IO00: J18.27(A14) ; also on sheet 6
GPIO1_IO01: J18.12(B6) ; also on sheet 6
GPIO1_IO05: J18.33(A17) ; also on sheet 6
GPIO1_IO06: J18.31(A16) ; also on sheet 6
GPIO1_IO07: J18.16(B8) ; also on sheet 6
GPIO1_IO08: J18.13(A7) ; also on sheet 6
GPIO1_IO09: J18.28(B14) ; also on sheet 6
GPIO1_IO11: J18.15(A8) ; also on sheet 6
GPIO1_IO12: J18.18(B9) ; also on sheet 6
GPIO1_IO15: J18.22(B11) ; also on sheet 6
I2C1_SCL: R493.1 R494.1 ; also on sheet 6 10
I2C1_SDA: R491.1 R492.1 ; also on sheet 6 10
I2C2_SCL: U58.2(A1) ; also on sheet 6 23
I2C2_SCL_3V3: R428.1 R475.2 U58.10(B1) ; also on sheet 20 24 25
I2C2_SDA: U58.3(A2) ; also on sheet 6 23
I2C2_SDA_3V3: R435.1 R476.2 U58.9(B2) ; also on sheet 20 24 25
I2C3_nINT: J27.5(A3) Q13.3(DRAIN) R334.2
I2C3_SCL: U58.4(A3) ; also on sheet 6 18 19
I2C3_SCL_3V3: J18.5(A3) J27.7(A4) R477.2 U58.8(B3) ; also on sheet 20 25
I2C3_SDA: U58.5(A4) ; also on sheet 6 18 19
I2C3_SDA_3V3: J18.3(A2) J27.9(A5) R478.2 U58.7(B4) ; also on sheet 20 25
IOEXP0-nINT: R495.2 U59.22(~{INT})
IOEXP0_nINT: R495.1 ; also on sheet 6
IOEXP1-nINT: R496.2 U60.22(~{INT})
IOEXP1_nINT: R496.1 ; also on sheet 6
IOEXP2-SCL: R494.2 U60.19(SCL)
IOEXP2-SDA: R492.2 U60.20(SDA)
IOEXP-SCL: R493.2 U59.19(SCL)
IOEXP-SDA: R491.2 U59.20(SDA)
KEYE_PCIe_nCLKREQ: R413.2 ; also on sheet 23
KEYE_PCIe_nDIS1: R416.2 R620.2 ; also on sheet 23
KEYE_PCIe_nDIS2: R623.2 ; also on sheet 23
KEYE_PCIe_nRST: R414.2 ; also on sheet 23
KEYE_PCIe_nWAKE: R421.2 ; also on sheet 23
KEYE_PCIE_RXN: R420.2 ; also on sheet 23
KEYE_PCIE_RXP: R418.2 ; also on sheet 23
KEYE_PCIE_TXN: C413.2 ; also on sheet 23
KEYE_PCIE_TXP: C410.2 ; also on sheet 23
KEYE_REF_CLK_32K: R419.2 ; also on sheet 23
KEYE_REF_CLKN: R425.2 ; also on sheet 23
KEYE_REF_CLKP: R424.2 ; also on sheet 23
KEYM_PCIe_nCLKREQ: R408.2 ; also on sheet 19
KEYM_PCIe_nDIS: R410.2 ; also on sheet 19
KEYM_PCIe_nRST: R412.2 ; also on sheet 19
KEYM_PCIE_nWAKE: U60.16(P1_6) ; also on sheet 19
KEYM_PCIE_RXN: R417.2 ; also on sheet 19
KEYM_PCIE_RXP: R415.2 ; also on sheet 19
KEYM_PCIE_TXN: C409.2 ; also on sheet 19
KEYM_PCIE_TXP: C408.2 ; also on sheet 19
KEYM_REF_CLKN: R422.2 ; also on sheet 19
KEYM_REF_CLKP: R423.2 ; also on sheet 19
LVDS0_BLT_EN: U59.10(P1_0) ; also on sheet 20
LVDS0_CTP_nINT: U62.16(B6) ; also on sheet 20
LVDS0_CTP_nINT_1V8: U62.8(A6) ; also on sheet 6
LVDS0_CTP_RST: U59.12(P1_2) ; also on sheet 20
LVDS1_BLT_EN: U59.11(P1_1) ; also on sheet 20
LVDS1_CTP_nINT: U62.15(B7) ; also on sheet 20
LVDS1_CTP_nINT_1V8: U62.9(A7) ; also on sheet 6
LVDS1_CTP_RST: U59.13(P1_3) ; also on sheet 20
M2_BT_WAKE_HOST: R441.2 ; also on sheet 23
M2_ECSPI2_MISO: R543.2 ; also on sheet 23
M2_ECSPI2_MOSI: R544.2 ; also on sheet 23
M2_ECSPI2_SCLK: R545.2 ; also on sheet 23
M2_ECSPI2_SS0: R542.2 ; also on sheet 23
M2_nALERT: R556.2 ; also on sheet 23
M2_PCM_CLK: R469.2 ; also on sheet 23
M2_PCM_IN: R470.2 ; also on sheet 23
M2_PCM_OUT: R468.2 ; also on sheet 23
M2_PCM_SYNC: R467.2 ; also on sheet 23
M2_SD_CLK: R427.2 ; also on sheet 23
M2_SD_CMD: R433.2 ; also on sheet 23
M2_SD_DATA0: R432.2 ; also on sheet 23
M2_SD_DATA1: R436.2 ; also on sheet 23
M2_SD_DATA2: R438.2 ; also on sheet 23
M2_SD_DATA3: R437.2 ; also on sheet 23
M2_SD_nRST: R443.2 ; also on sheet 23
M2_SD_WAKE_HOST: R439.2 ; also on sheet 23
M2_UART_CTS: R457.2 ; also on sheet 23
M2_UART_RTS: R461.2 ; also on sheet 23
M2_UART_RXD: R455.2 ; also on sheet 23
M2_UART_TXD: R459.2 ; also on sheet 23
ONOFF: J27.4(B2) R330.1 TP142.1(Pin1) ; also on sheet 8
PCIE_CLKN: R429.2 R431.1 ; also on sheet 7
PCIE_CLKP: R426.2 R430.1 ; also on sheet 7
PCIE_DIG1: C411.1 C412.1 C422.1 R409.2 R411.2 U55.7(VDDDIG1.8) U56.6(VCC)
PCIe_nCLKREQ: R483.2 U61.2(A1) ; also on sheet 6
PCIe_nCLKREQ_3V3: R408.1 R413.1 R458.1 R487.2 TP159.1(Pin1) U56.2(A) U61.10(B1)
PCIe_nDIS: U63.2(A1) ; also on sheet 6
PCIe_nDIS_3V3: R410.1 R416.1 U63.10(YB1)
PCIe_nRST: R498.2 U63.3(A2) ; also on sheet 6
PCIe_nRST_3V3: R412.1 R414.1 U63.9(YB2)
PCIe_nWAKE: R484.2 U61.3(A2) ; also on sheet 6
PCIe_nWAKE_3V3: R421.1 R488.2 U61.9(B2)
PCIE_REQ: R442.1 R444.1 R458.2 U56.4(Y)
PCIE_RXN: R417.1 R420.1 ; also on sheet 7
PCIE_RXP: R415.1 R418.1 ; also on sheet 7
PCIE_TXN: C409.1 C413.1 ; also on sheet 7
PCIE_TXP: C408.1 C410.1 ; also on sheet 7
PCM_CLK: R469.1 R472.1 ; also on sheet 6
PCM_IN: R470.1 R474.1 ; also on sheet 6
PCM_OUT: R468.1 R473.1 ; also on sheet 6
PCM_SYNC: R467.1 R471.1 ; also on sheet 6
PMIC_32K_OUT: R499.1 ; also on sheet 10
POR_B: R466.1 U57.2(A) ; also on sheet 8 10 24
REF_CLK_32K: R499.2 U63.4(A3)
REF_CLK_32K_3V3: R419.1 U63.8(YB3)
REF_CLKN_CN: R422.1 R425.1 R431.2 R440.2
REF_CLKP_CN: R423.1 R424.1 R430.2 R434.2
RLED_GPIO: R344.1 U59.15(P1_5)
RTC_nINTA: U60.4(P0_3) ; also on sheet 24
SAI1_MCLK: J18.26(B13) ; also on sheet 6
SAI1_RXC: R568.1 ; also on sheet 6
SAI1_RXFS: R566.1 ; also on sheet 6
SAI5_MCLK: J18.29(A15) ; also on sheet 6
SAI5_RXC: J18.40(B20) ; also on sheet 6
SAI5_RXD0: J18.38(B19) ; also on sheet 6
SAI5_RXD1: J18.37(A19) ; also on sheet 6
SAI5_RXD2: J18.36(B18) ; also on sheet 6
SAI5_RXD3: J18.35(A18) ; also on sheet 6
SAI5_RXFS: J18.32(B16) ; also on sheet 6
SD1_CLK: R427.1 R446.1 ; also on sheet 6
SD1_CMD: R433.1 R447.1 ; also on sheet 6
SD1_DATA0: R432.1 R448.1 ; also on sheet 6
SD1_DATA1: R436.1 R449.1 ; also on sheet 6
SD1_DATA2: R438.1 R450.1 ; also on sheet 6
SD1_DATA3: R437.1 R451.1 ; also on sheet 6
SD2-CLK: C353.1 J17.5(CLK) R326.2 U47.1(CH1) U47.10(NC4)
SD2-CMD: J17.3(CMD) R325.2 U46.4(CH3) U46.7(NC2)
SD2-DATA0: J17.7(DATA0) R327.2 U47.2(CH2) U47.9(NC3)
SD2-DATA1: J17.8(DATA1) R328.2 U47.4(CH3) U47.7(NC2)
SD2-DATA2: J17.1(DATA2) R324.2 U46.1(CH1) U46.10(NC4)
SD2-DATA3: J17.2(CD/DATA3) R323.2 U46.2(CH2) U46.9(NC3)
SD2-nCD: J17.9(CD) R329.2 U47.5(CH4) U47.6(NC1)
SD2_CLK: R326.1 ; also on sheet 6
SD2_CMD: R325.1 ; also on sheet 6
SD2_DATA0: R327.1 ; also on sheet 6
SD2_DATA1: R328.1 ; also on sheet 6
SD2_DATA2: R324.1 ; also on sheet 6
SD2_DATA3: R323.1 ; also on sheet 6
SD2_nCD: R329.1 ; also on sheet 6
SD_nRST: R443.1 R454.1 ; also on sheet 6
SD_WAKE_HOST: R439.1 R453.1 ; also on sheet 6
SPI_EXP_SEL: R574.1 U60.7(P0_6) U102.15(SEL)
SPI_nINT_1V8: R556.1 R557.1 R558.2 U104.7(A3)
SPI_nINT_3V3: R559.2 U60.15(P1_5) U104.14(B3)
SPK_PWREN: U59.14(P1_4) ; also on sheet 18
SYS_nRST: J27.3(A2) R331.1 TP143.1(Pin1) ; also on sheet 10 24
UART1_CTS: R457.1 R464.1 ; also on sheet 6
UART1_RTS: R461.1 R465.1 ; also on sheet 6
UART1_RXD: R455.1 R462.1 ; also on sheet 6
UART1_TXD: R459.1 R463.1 ; also on sheet 6
UART3_CTS: J18.7(A4) ; also on sheet 6
UART3_RTS: J18.11(A6) ; also on sheet 6
UART3_RXD: J18.10(B5) ; also on sheet 6
UART3_TXD: J18.8(B4) ; also on sheet 6
USB1_SS_SEL: U60.5(P0_4) ; also on sheet 13
USB2_PWR_EN: U60.6(P0_5) ; also on sheet 14
USER_KEY: R332.2 R335.1 TP144.1(Pin1) ; also on sheet 6
VSD_3V3: C351.1 C352.1 J17.4(VDD) U46.5(CH4) U46.6(NC1) ; also on sheet 10
W2_BT_RST: U62.6(A4) ; also on sheet 21
W2_BT_RST_3V3: R622.2 U62.18(B4)
W2_BT_WAKE_HOST: R452.2 ; also on sheet 21
W2_ECSPI2_MISO: R548.2 ; also on sheet 21
W2_ECSPI2_MOSI: R547.2 ; also on sheet 21
W2_ECSPI2_SCLK: R549.2 ; also on sheet 21
W2_ECSPI2_SS0: R546.2 ; also on sheet 21
W2_HOST_WAKE_BT: U62.4(A2) ; also on sheet 21
W2_HOST_WAKE_BT_3V3: U60.11(P1_1) U62.20(B2)
W2_HOST_WAKE_SD: U62.3(A1) ; also on sheet 21
W2_HOST_WAKE_SD_3V3: U60.10(P1_0) U62.21(B1)
W2_PCM_CLK: R472.2 ; also on sheet 21
W2_PCM_IN: R474.2 ; also on sheet 21
W2_PCM_OUT: R473.2 ; also on sheet 21
W2_PCM_SYNC: R471.2 ; also on sheet 21
W2_PDN: U62.5(A3) ; also on sheet 21
W2_PDN_3V3: R621.2 U62.19(B3)
W2_RST_IND: U104.8(A4) ; also on sheet 21
W2_RST_IND_3V3: U60.14(P1_4) U104.13(B4)
W2_SD_CLK: R446.2 ; also on sheet 21
W2_SD_CMD: R447.2 ; also on sheet 21
W2_SD_DATA0: R448.2 ; also on sheet 21
W2_SD_DATA1: R449.2 ; also on sheet 21
W2_SD_DATA2: R450.2 ; also on sheet 21
W2_SD_DATA3: R451.2 ; also on sheet 21
W2_SD_nRST: R454.2 ; also on sheet 21
W2_SD_WAKE_HOST: R453.2 ; also on sheet 21
W2_SPI_nINT: R557.2 ; also on sheet 21
W2_UART_CTS: R465.2 ; also on sheet 21
W2_UART_RTS: R464.2 ; also on sheet 21
W2_UART_RXD: R462.2 ; also on sheet 21
W2_UART_TXD: R463.2 ; also on sheet 21
WB_ECSPI2_MISO: U98.14(B3) U102.9(S3A)
WB_ECSPI2_MOSI: U98.15(B2) U102.3(S2A)
WB_ECSPI2_SCLK: U98.13(B4) U102.12(S4A)
WB_ECSPI2_SS0: U98.16(B1) U102.16(S1A)
N110606000: D16.3(CATHODE3) R336.1
N110606002: D16.4(CATHODE2) R337.1
N110606004: D16.1(CATHODE1) R338.1
N110606046: Q16.3(DRAIN) R337.2
N110606048: Q14.3(DRAIN) R338.2
N110606050: Q15.3(DRAIN) R336.2
N110606096: Q15.1(GATE) R339.2 R340.1
N110606102: Q16.1(GATE) R341.1 R343.2
N110606110: Q14.1(GATE) R342.1 R344.2
N110607202: R330.2 SW6.3(B1) SW6.4(B2)
N110607216: R331.2 SW7.3(B1) SW7.4(B2)
N110607507: R335.2 SW8.3(B1) SW8.4(B2)
N111081548: R428.2 U55.8(SCLK_3.3)
N111081549: R435.2 U55.9(SDATA_3.3)
N111081552: C417.1 C418.1 C419.1 FB14.2 U55.11(VDD1.8_1) U55.20(VDD1.8_2)
N111081600: R456.2 R460.2 U55.5(GNDREF)
N111081634: C420.1 U55.1(X1_25) Y4.3
N111081636: C421.1 U55.2(X2) Y4.1
N111081637: C414.1 C415.1 C416.1 FB13.2 U55.3(VDDXTAL1.8) U55.16(VDDA1.8)
N111081642: R426.1 U55.13(DIF0)
N111081643: TP158.1(Pin1) U55.4(SADR/REF1.8)
N111081644: R429.1 U55.14(~{DIF0})
N111081645: R434.1 U55.17(DIF1)
N111081646: R440.1 U55.18(~{DIF1})
N111081673: R444.2 U55.19(~{OE1})
N111081674: R442.2 U55.12(~{OE0})
N111081684: R445.2 U55.23(SS_EN_TRI)
N111100057: R479.2 U58.12(OE)
N111100374: R497.2 U61.12(OE)
N111271923: R480.2 U60.18(ADDR)
N111548300: R500.1 U62.2(DIR)
N111626487: R501.1 U63.12(~{OE})
N112007145: R552.1 U98.9(DIR4)
N112007159: R553.1 U98.1(DIR2)
N112007171: R550.1 U98.11(~{OE})
N112007178: R551.1 U98.4(DIR1)
N112014194: R554.2 U98.12(DIR3)
N112113252: R575.1 U102.13(EN)
N112670014: R591.1 U104.1(DIR2)
N112670016: R589.1 U104.11(~{OE})
N112670023: R590.1 U104.4(DIR1)
N112676213: R624.1 U104.12(DIR3)
N112681857: R625.1 U104.9(DIR4)

Not connected (* = marked no-connect by the designer): U56 5(NC)*; U57 5(NC)*; U59 8(P0_7)*; U60 1(P0_0)* 2(P0_1)* 8(P0_7)* 17(P1_7)*; U62 7(A5)* 10(A8)* 14(B8)* 17(B5)*; U63 5(YA4)* 7(B4)*

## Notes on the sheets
sheet 26
- PCIe3.0 CLK
- CPU CLK
- Internal PU
- PD
- Internal
- PD
- PD 120K
- M.2 CLK
- NOTE:
  Use external clock as default.
  When using internal clockpopulate R430, R431, remove R426, R429, R434, R440.
- 1.8V
- 7bit 0x6Ah 0x1101010
- 1.8V
- 1.8V
- 1. For L1 Sub-states: Uses a bidirectional open-drain clock request (CLKREQ#)
  signal for entry and exit this state.
- 2. Clock delay should be smaller than 400ns, according to M.2 spec,
  so CLKREQ# should be connected to OE pins instead of PD pin.
- I2C Level shifter
- WIFI&BT Module PDN
- BT_INDEPENDENT_RESET
- IO Expansion
- 1.8V
- I2C IO EXP
- I2C IO EXP
- DIR:
  H: An -> Bn
  L: Bn -> An
- 7bit 0x20h 0x0100000
- 7bit 0x21h 0x0100001
- IO Level shifter
- DIR:
  H: An -> Bn
  L: Bn -> An
- OE=H: Hi-Z; OE=L: enabled
  DIR=H, A -> B
  DIR=L, B -> A(Default)
sheet 27
- TF Card Slot
- EXP GPIO
- I2C3_SDA_3V3
- I2C3_SCL_3V3
- UART3_CTS
- UART3_RXD
- UART3_TXD
- UART3_RTS
- ECSPI2_MOSI
- TF Card Insert CD: Low
  TF Card WithOut CD: High
- ECSPI2_MISO
- ECSPI2_SCLK
- ECSPI2_SS0
- PWM4_3V3 SAI5_RXFS
- PDM_STREAM_3 SAI5_RXD3
- PDM_STREAM_2 SAI5_RXD2
- PDM_STREAM_1 SAI5_RXD1
- PDM_STREAM_0 SAI5_RXD0
- PDM_CLK SAI5_RXC
- Buttons
- # CPU ONOFF Button
- ONOFF
- # System Reset Button
- RESET
- WIFI&BT
- ECSPI2_MOSI
- ECSPI2_SS0
- ECSPI2_MISO
- # User Defined Button
- ECSPI2_SCLK
- USER KEY
- ECSPI2_SS0
- ECSPI2_MISO
- ECSPI2_MOSI
- ECSPI2_SCLK
- SEL=H:  SxB->Dx
  SEL=L:   SxA->Dx
- EXP GPIO
- 2
- 4
- +
- B
- R
- G
- 1
- 3
- RGB LED
